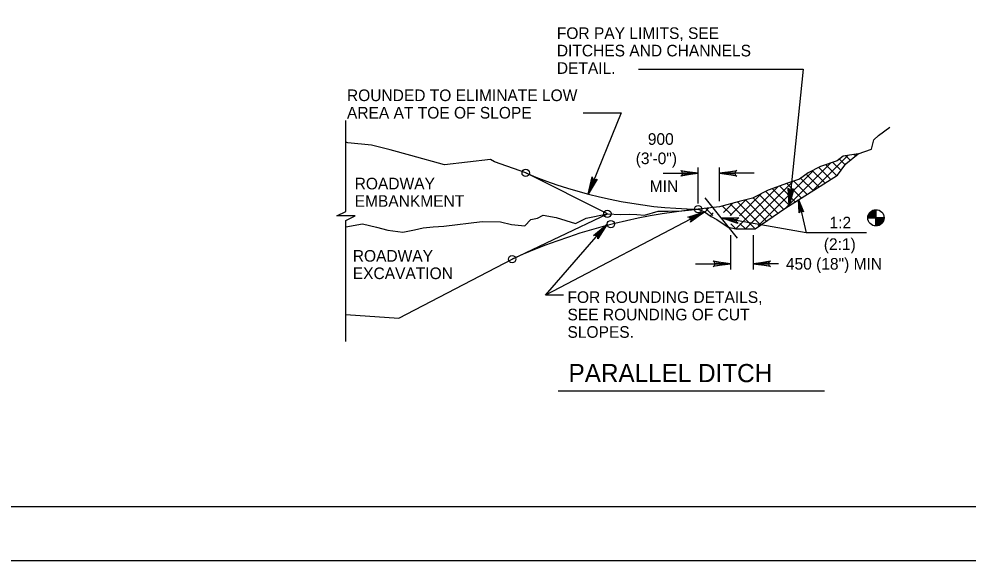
# Model space of a CAD drawing. Extents: x 240 to 1147, y 662 to 1256.
# Drawn here: x 597 to 858.8, y 662 to 811.2 of the extents above; entities that cross this region are included whole.
import ezdxf

# ---------------------------------------------------------------- set-up
doc = ezdxf.new("R2010")
doc.units = 0
for name, color, linetype in [('1', 7, 'Continuous'), ('2', 7, 'Continuous'), ('3', 7, 'Continuous'), ('PLT-BNDY', 7, 'Continuous')]:
    doc.layers.add(name, color=color, linetype=linetype)

msp = doc.modelspace()

# ---------------------------------------------------------------- linework, layer by layer
at = {"layer": '1'}
for points in [[(1065.4425, 677.018625), (1065.4425, 1241.018625), (279.4425, 1241.018625), (279.4425, 677.018625), (1065.4425, 677.018625), (1065.4425, 703.377625), (865.4425, 703.377625), (865.4425, 768.055125), (1065.4425, 768.055125), (1065.4425, 797.018625), (865.4425, 797.018625), (865.4425, 677.018625), (944.244, 677.018625), (944.244, 703.377625), (944.244, 677.018625), (1021.244, 677.018625), (1021.244, 703.377625), (1021.244, 691.061125), (1065.4425, 691.061125)], [(756.089, 767.017125), (755.7225, 766.985875), (753.8515, 763.027625), (756.089, 767.017125), (756.362, 767.158875), (753.8515, 763.027625), (755.2975, 767.154625), (755.05575, 767.423375), (753.8515, 763.027625), (754.9475, 767.733875), (755.05575, 767.423375)], [(779.5995, 769.325625), (779.76825, 768.996375), (784.14125, 768.756875), (779.5995, 769.325625), (779.36625, 769.525625), (784.14125, 768.756875), (779.7725, 768.540125), (779.612, 768.215125), (784.14125, 768.756875), (779.36625, 767.998375), (779.612, 768.215125)], [(794.56825, 768.185875), (794.3995, 768.515125), (790.02875, 768.756875), (794.56825, 768.185875), (794.8015, 767.985875), (790.02875, 768.756875), (794.39525, 768.971375), (794.55575, 769.296375), (790.02875, 768.756875), (794.8015, 769.515125), (794.55575, 769.296375)], [(810.25575, 764.296375), (809.912, 764.163125), (809.22875, 759.838125), (810.25575, 764.296375), (810.47875, 764.508875), (809.22875, 759.838125), (809.45775, 764.204625), (809.1495, 764.396375), (809.22875, 759.838125), (808.95775, 764.663125), (809.1495, 764.396375)], [(812.137, 758.102625), (812.3495, 758.279625), (811.80375, 761.519375), (812.137, 758.102625), (812.02875, 757.898375), (811.80375, 761.519375), (812.68275, 758.358875), (812.9475, 758.296375), (811.80375, 761.519375), (813.1475, 758.150625), (812.9475, 758.296375)], [(781.637, 756.565125), (781.939, 756.352625), (785.9245, 758.165125), (781.637, 756.565125), (781.339, 756.633875), (785.9245, 758.165125), (782.15575, 755.948375), (782.164, 755.585875), (785.9245, 758.165125), (782.0475, 755.279625), (782.164, 755.585875)], [(794.87475, 755.183875), (794.765, 755.535625), (790.5015, 756.527625), (794.87475, 755.183875), (795.0705, 754.946625), (790.5015, 756.527625), (794.83975, 755.986625), (795.054, 756.279625), (790.5015, 756.527625), (795.33275, 756.451125), (795.054, 756.279625)], [(755.66625, 751.715125), (756.0245, 751.625625), (759.0765, 754.765125), (755.66625, 751.715125), (755.362, 751.669375), (759.0765, 754.765125), (756.3725, 751.327625), (756.512, 750.994375), (759.0765, 754.765125), (756.51625, 750.667125), (756.512, 750.994375)], [(788.51, 744.429625), (788.67875, 744.100625), (793.0515, 743.858875), (788.51, 744.429625), (788.27875, 744.627625), (793.0515, 743.858875), (788.68275, 743.644375), (788.5245, 743.317125), (793.0515, 743.858875), (788.27875, 743.100625), (788.5245, 743.317125)], [(803.84125, 743.290125), (803.6725, 743.617125), (799.3015, 743.858875), (803.84125, 743.290125), (804.0745, 743.090125), (799.3015, 743.858875), (803.66825, 744.075625), (803.82875, 744.400625), (799.3015, 743.858875), (804.0745, 744.617125), (803.82875, 744.400625)]]:
    msp.add_lwpolyline(points, dxfattribs=at)
at = {"layer": '2'}
for p, q in [((767.742, 797.449875), (813.0655, 797.449875)), ((813.0655, 797.449875), (809.22875, 759.838125)), ((752.49525, 785.403375), (762.95225, 785.403375)), ((762.95225, 785.403375), (753.8515, 763.027625)), ((815.94525, 764.221375), (825.3765, 773.650625)), ((824.4475, 771.263125), (823.07025, 772.640125)), ((825.91625, 772.446375), (824.8015, 773.558875)), ((827.464, 773.550625), (827.089, 773.925625)), ((784.14125, 760.458875), (784.14125, 770.356875)), ((790.02875, 761.075625), (790.02875, 770.356875)), ((808.314, 759.240125), (820.60575, 771.533875)), ((820.537, 767.217125), (817.41825, 770.335875)), ((822.14125, 768.265125), (819.31, 771.096375)), ((823.4765, 769.581875), (821.29325, 771.765125)), ((759.14125, 757.608875), (736.64125, 768.858875)), ((774.54125, 768.756875), (784.14125, 768.756875)), ((799.62875, 768.756875), (790.02875, 768.756875)), ((800.68075, 754.258875), (815.76825, 769.346375)), ((815.7245, 764.077625), (812.44525, 767.354625)), ((817.32875, 765.123375), (814.10375, 768.348375)), ((818.93275, 766.171375), (815.76, 769.342125)), ((794.4765, 753.358875), (806.1475, 765.029625)), ((797.12875, 753.358875), (810.2515, 766.481875)), ((809.30575, 759.888125), (804.68275, 764.510875)), ((810.91, 760.935875), (806.64125, 765.204625)), ((812.514, 761.981875), (808.5995, 765.896375)), ((814.12025, 763.029625), (810.55775, 766.590125)), ((795.0405, 750.888375), (786.12925, 761.956625)), ((795.54925, 757.083625), (801.62025, 763.154625)), ((804.49125, 756.746375), (799.2725, 761.967125)), ((806.0975, 757.794375), (801.03275, 762.856875)), ((807.7015, 758.840125), (802.79525, 763.748375)), ((785.9495, 758.090125), (787.02025, 759.158875)), ((793.44125, 757.189875), (790.90775, 759.723375)), ((791.151, 757.987875), (793.67025, 760.506875)), ((792.9555, 757.141875), (797.25375, 761.440125)), ((799.67875, 753.604625), (792.9745, 760.308875)), ((801.28275, 754.652625), (795.04125, 760.894375)), ((802.887, 755.700625), (797.16825, 761.419375)), ((732.89125, 745.108875), (759.14125, 757.608875)), ((788.187, 757.142125), (786.2495, 759.079625)), ((787.56, 757.048875), (788.333, 757.821875)), ((830.89875, 756.486375), (835.3885, 756.486375)), ((835.3885, 756.486375), (830.89875, 756.486375)), ((830.89875, 756.484375), (835.3885, 756.484375)), ((835.3885, 756.484375), (830.89875, 756.484375)), ((833.1425, 754.240625), (833.1425, 758.730125)), ((833.1425, 758.728125), (833.1425, 754.240625)), ((833.14475, 754.240625), (833.14475, 758.730125)), ((833.14475, 758.728125), (833.14475, 754.240625)), ((794.6225, 753.358875), (793.152, 754.828875)), ((797.2725, 753.358875), (795.6675, 754.963625)), ((793.0515, 751.758875), (793.0515, 742.258875)), ((799.3015, 751.758875), (799.3015, 742.258875)), ((830.52575, 752.392875), (813.89575, 752.392875)), ((701.64125, 728.858875), (732.89125, 745.108875)), ((783.4515, 743.858875), (793.0515, 743.858875)), ((806.2845, 743.858875), (799.3015, 743.858875)), ((687.1245, 729.894375), (701.64125, 728.858875)), ((745.589, 708.846125), (819.00575, 708.846125))]:
    msp.add_line(p, q, dxfattribs=at)
for points in [[(687.1245, 722.456875), (687.1245, 755.756875), (689.6245, 757.006875), (684.6245, 757.006875), (687.1245, 758.256875), (687.1245, 783.256875)], [(687.1245, 754.021375), (691.63275, 754.827625), (695.487, 753.885875), (698.67875, 753.079625), (702.7995, 752.540125), (705.989, 753.213125), (708.38275, 753.750625), (711.1745, 754.021375), (714.0975, 754.154625), (724.5995, 755.498375), (729.6515, 755.365125), (732.70775, 754.692125), (736.43075, 754.290125), (738.0265, 756.038125), (739.887, 756.440125), (741.48275, 757.248375), (745.0725, 756.575625), (750.389, 754.960875), (753.314, 756.440125), (759.14125, 757.608875), (762.7515, 757.381875), (765.14325, 757.517125), (767.27025, 757.381875), (769.3975, 757.248375), (773.12025, 758.323375), (775.912, 758.323375), (779.635, 758.458875), (784.14125, 758.858875), (785.9245, 758.165125), (787.717, 756.814875), (789.263, 756.010875), (792.39525, 753.885875), (794.5225, 753.481875), (797.4475, 753.481875), (799.839, 753.481875), (808.3475, 759.265125), (816.05775, 764.104625), (822.57025, 768.273375), (824.83075, 771.367125), (828.2475, 774.108875), (831.8765, 775.400625), (832.54125, 777.956875), (833.87025, 779.167125), (836.92875, 781.452625)], [(736.64125, 768.858875), (728.05575, 771.925625), (726.9765, 772.581875), (714.237, 771.052625), (704.9515, 773.673375), (699.337, 775.202625), (694.15375, 776.513125), (687.6765, 777.167125), (687.1245, 777.335875)], [(828.2475, 774.108875), (824.14525, 773.454625), (822.41825, 772.144375), (817.88275, 770.615125), (814.42875, 768.867125), (812.05375, 767.119375), (808.814, 766.027625), (803.41625, 764.063125), (799.0975, 761.877625), (795.4265, 761.004625), (790.02875, 759.475625), (784.14125, 758.858875)], [(811.80375, 761.519375), (813.89575, 752.392875), (790.5015, 756.527625)], [(785.9245, 758.165125), (742.064, 735.221375)], [(833.13625, 758.609375), (832.84675, 758.592625), (832.58, 758.523875), (832.33225, 758.444875), (832.078, 758.321875), (831.83425, 758.165625), (831.60725, 757.973875), (831.43, 757.759375), (831.255, 757.490625), (831.1405, 757.228125), (831.04675, 756.936375), (831.00725, 756.676125), (831.003, 756.478125)], [(833.13625, 758.451125), (832.87175, 758.434375), (832.62375, 758.371875), (832.3925, 758.296875), (832.155, 758.182375), (831.928, 758.036375), (831.71975, 757.861375), (831.55925, 757.663625), (831.39675, 757.413625), (831.2885, 757.171875), (831.203, 756.898875), (831.1675, 756.663625), (831.1635, 756.478125)], [(833.13625, 758.290625), (832.89675, 758.276125), (832.66975, 758.217625), (832.451, 758.146875), (832.23425, 758.042625), (832.02375, 757.907375), (831.83425, 757.748875), (831.6885, 757.569875), (831.53625, 757.338625), (831.4385, 757.115625), (831.35925, 756.863625), (831.326, 756.648875), (831.32175, 756.478125)], [(833.13625, 758.130125), (832.92175, 758.117625), (832.7135, 758.065625), (832.51125, 757.998875), (832.31125, 757.903125), (832.1175, 757.778125), (831.94875, 757.636375), (831.8175, 757.476125), (831.676, 757.261375), (831.5885, 757.059375), (831.5155, 756.828125), (831.48625, 756.634375), (831.48225, 756.478125)], [(833.13625, 757.971875), (832.94675, 757.959375), (832.75725, 757.911375), (832.57175, 757.851125), (832.3885, 757.763625), (832.2135, 757.651125), (832.0635, 757.523875), (831.94675, 757.380125), (831.8175, 757.184375), (831.7385, 757.003125), (831.67175, 756.790625), (831.64475, 756.619875), (831.6405, 756.478125)], [(833.13625, 757.811375), (832.97175, 757.801125), (832.801, 757.759375), (832.63, 757.703125), (832.4675, 757.623875), (832.30725, 757.521875), (832.178, 757.411375), (832.076, 757.286375), (831.95725, 757.109375), (831.88625, 756.946875), (831.826, 756.755125), (831.803, 756.607375), (831.801, 756.478125)], [(833.13625, 757.651125), (832.99675, 757.642625), (832.84475, 757.605125), (832.6905, 757.555125), (832.54475, 757.484375), (832.401, 757.392625), (832.2925, 757.298875), (832.203, 757.192625), (832.09875, 757.032375), (832.03625, 756.890625), (831.98225, 756.717625), (831.9635, 756.592625), (831.95925, 756.478125)], [(833.13625, 757.492625), (833.02175, 757.484375), (832.8905, 757.451125), (832.74875, 757.407375), (832.62375, 757.344875), (832.49675, 757.263625), (832.405, 757.188625), (832.33225, 757.096875), (832.2385, 756.955125), (832.18625, 756.834375), (832.1385, 756.682375), (832.12175, 756.578125), (832.11975, 756.478125)], [(833.13625, 757.332375), (833.04675, 757.326125), (832.93425, 757.298875), (832.80925, 757.257375), (832.701, 757.205125), (832.5925, 757.136375), (832.51975, 757.076125), (832.46125, 757.003125), (832.38, 756.880125), (832.33625, 756.778125), (832.2925, 756.644875), (832.28225, 756.563625), (832.28, 756.478125)], [(833.13625, 757.171875), (833.07175, 757.167625), (832.978, 757.144875), (832.86975, 757.109375), (832.78, 757.065625), (832.68625, 757.007375), (832.63425, 756.963625), (832.5905, 756.909375), (832.51975, 756.803125), (832.48425, 756.721875), (832.44875, 756.609375), (832.4405, 756.551125), (832.4385, 756.478125)], [(833.13625, 757.013625), (833.09475, 757.009375), (833.02175, 756.990625), (832.928, 756.961375), (832.85725, 756.926125), (832.78, 756.878125), (832.74875, 756.851125), (832.71975, 756.815625), (832.66125, 756.726125), (832.63425, 756.665625), (832.605, 756.573875), (832.59875, 756.536375), (832.59875, 756.478125)], [(832.7675, 756.484375), (832.7675, 756.501125), (832.78225, 756.555125), (832.80725, 756.632375), (832.83225, 756.686375), (832.87175, 756.744875), (832.88225, 756.759375), (832.901, 756.773875), (832.96975, 756.819875), (833.01125, 756.836375), (833.08425, 756.859375), (833.09875, 756.861375), (833.1425, 756.863625)], [(833.13625, 756.690625), (833.11125, 756.684375), (833.04675, 756.665625), (833.0135, 756.648875), (832.976, 756.623875), (832.9425, 756.573875), (832.93225, 756.553125), (832.9175, 756.503125), (832.9175, 756.478125)], [(833.09875, 756.478125), (833.101, 756.507375), (833.103, 756.526125), (833.105, 756.526125), (833.11125, 756.536375), (833.1135, 756.536375), (833.13, 756.546875), (833.13, 756.546875)], [(833.51975, 756.486375), (833.51975, 756.469875), (833.505, 756.415625), (833.48, 756.336375), (833.455, 756.284375), (833.4155, 756.226125), (833.405, 756.211375), (833.3885, 756.196875), (833.3175, 756.151125), (833.276, 756.134375), (833.203, 756.111375), (833.1885, 756.109375), (833.14475, 756.107375)], [(833.151, 754.359375), (833.4405, 754.378125), (833.70725, 754.446875), (833.955, 754.526125), (834.20925, 754.648875), (834.453, 754.805125), (834.68225, 754.996875), (834.85725, 755.211375), (835.03225, 755.480125), (835.14875, 755.742625), (835.2405, 756.034375), (835.28, 756.294875), (835.28425, 756.492625)], [(833.151, 754.519875), (833.4155, 754.536375), (833.6635, 754.598875), (833.89475, 754.673875), (834.13225, 754.788625), (834.35925, 754.934375), (834.5675, 755.109375), (834.728, 755.307375), (834.8925, 755.555125), (834.99875, 755.798875), (835.08425, 756.071875), (835.11975, 756.307375), (835.126, 756.492625)], [(833.151, 754.680125), (833.3905, 754.694875), (833.61975, 754.753125), (833.83625, 754.821875), (834.053, 754.928125), (834.2635, 755.063625), (834.453, 755.221875), (834.59875, 755.401125), (834.751, 755.632375), (834.84875, 755.855125), (834.928, 756.107375), (834.96125, 756.321875), (834.9655, 756.492625)], [(833.151, 754.838625), (833.3655, 754.853125), (833.576, 754.905125), (833.776, 754.971875), (833.976, 755.067625), (834.16975, 755.190625), (834.3385, 755.334375), (834.46975, 755.494875), (834.61125, 755.709375), (834.69875, 755.911375), (834.77175, 756.142625), (834.803, 756.336375), (834.805, 756.492625)], [(833.151, 754.998875), (833.3405, 755.011375), (833.53, 755.059375), (833.7175, 755.119875), (833.89875, 755.207375), (834.076, 755.319875), (834.22375, 755.446875), (834.3405, 755.590625), (834.46975, 755.784375), (834.551, 755.967625), (834.6175, 756.180125), (834.6425, 756.348875), (834.64675, 756.492625)], [(833.151, 755.159375), (833.3155, 755.169875), (833.48625, 755.211375), (833.65725, 755.267625), (833.81975, 755.346875), (833.98, 755.448875), (834.11125, 755.559375), (834.2135, 755.684375), (834.33, 755.861375), (834.401, 756.023875), (834.46125, 756.215625), (834.48425, 756.363625), (834.48625, 756.492625)], [(833.151, 755.317625), (833.2905, 755.328125), (833.4425, 755.365625), (833.59675, 755.415625), (833.7425, 755.486375), (833.88625, 755.578125), (833.99675, 755.669875), (834.08425, 755.778125), (834.1885, 755.938625), (834.251, 756.080125), (834.305, 756.253125), (834.326, 756.378125), (834.328, 756.492625)], [(833.151, 755.478125), (833.2655, 755.484375), (833.39875, 755.519875), (833.5385, 755.563625), (833.6635, 755.626125), (833.7905, 755.705125), (833.88225, 755.782375), (833.955, 755.871875), (834.04875, 756.013625), (834.101, 756.136375), (834.14875, 756.288625), (834.1655, 756.392625), (834.1675, 756.492625)], [(833.151, 755.638625), (833.2405, 755.642625), (833.353, 755.671875), (833.478, 755.711375), (833.58625, 755.765625), (833.69675, 755.834375), (833.7675, 755.894875), (833.826, 755.967625), (833.90725, 756.090625), (833.953, 756.192625), (833.99475, 756.323875), (834.00725, 756.405125), (834.00925, 756.492625)], [(833.151, 755.796875), (833.2175, 755.801125), (833.30925, 755.826125), (833.41975, 755.861375), (833.50725, 755.903125), (833.601, 755.963625), (833.653, 756.007375), (833.69675, 756.061375), (833.7675, 756.167625), (833.803, 756.248875), (833.8385, 756.361375), (833.84675, 756.419875), (833.84875, 756.492625)], [(833.151, 755.957375), (833.1925, 755.959375), (833.2655, 755.978125), (833.35925, 756.009375), (833.43, 756.042625), (833.50725, 756.092625), (833.5405, 756.119875), (833.56975, 756.155125), (833.626, 756.242625), (833.653, 756.305125), (833.68225, 756.396875), (833.6885, 756.434375), (833.6905, 756.492625)], [(833.151, 756.278125), (833.178, 756.284375), (833.2405, 756.305125), (833.27375, 756.321875), (833.3135, 756.346875), (833.34475, 756.396875), (833.355, 756.417625), (833.36975, 756.467625), (833.36975, 756.492625)], [(833.1885, 756.492625), (833.1885, 756.463625), (833.18425, 756.444875), (833.18425, 756.442625), (833.176, 756.434375), (833.176, 756.434375), (833.15725, 756.421875), (833.15725, 756.421875)], [(747.064, 735.221375), (742.064, 735.221375), (759.0765, 754.765125)]]:
    msp.add_lwpolyline(points, dxfattribs=at)
for centre, radius in [((736.640417, 768.858125), 1.015435), ((784.140417, 758.858125), 1.015435), ((759.140417, 757.608125), 1.015435), ((833.143012, 756.48598), 2.24484), ((833.143012, 756.484386), 2.24484), ((833.14467, 756.48598), 2.24484), ((833.14467, 756.484386), 2.24484), ((760.092917, 754.764625), 1.015435), ((732.890417, 745.108125), 1.015435)]:
    msp.add_circle(centre, radius, dxfattribs=at)
for centre, radius, start, end in [((786.398894, 887.398393), 128.560107, 247.22928056, 268.99340556), ((800.2654, 596.369552), 163.286716, 95.66733889, 114.369375)]:
    msp.add_arc(centre, radius, start, end, dxfattribs=at)
at = {"layer": 'PLT-BNDY'}
msp.add_lwpolyline([(240.4425, 1256.018625), (1081.4425, 1256.018625), (1081.4425, 662.018625), (240.4425, 662.018625)], close=True, dxfattribs=at)

# ---------------------------------------------------------------- texts
at = {"layer": '1'}
for s, p in [('(3\'-0")', (766.95425, 771.269875)), ('(2:1)', (818.776, 747.647125))]:
    msp.add_text(s, height=3.1999995, dxfattribs=at).set_placement(p)
at = {"layer": '2'}
for s, p in [('900', (770.288835, 776.582125)), ('450 (18") MIN', (808.332019, 742.230375))]:
    msp.add_text(s, height=3.1999995, dxfattribs=at).set_placement(p)
at = {"layer": '3'}
for s, height, p in [('FOR PAY LIMITS, SEE', 3.1999995, (745.221, 805.724875)), ('DITCHES AND CHANNELS', 3.1999995, (745.221, 800.926875)), ('DETAIL.', 3.1999995, (745.221, 796.128875)), ('ROUNDED TO ELIMINATE LOW', 3.1999875, (687.38975, 788.620625)), ('AREA AT TOE OF SLOPE', 3.1999875, (687.38975, 783.820625)), ('ROADWAY', 3.1999875, (689.514, 764.321375)), ('MIN', 3.1999995, (770.81375, 763.608625)), ('EMBANKMENT', 3.1999875, (689.514, 759.521375)), ('1:2', 3.1999995, (820.352, 753.576625)), ('ROADWAY', 3.1999875, (688.99525, 744.417125)), ('EXCAVATION', 3.1999875, (688.99525, 739.617125)), ('FOR ROUNDING DETAILS,', 3.1999995, (748.1515, 733.056875)), ('SEE ROUNDING OF CUT', 3.1999995, (748.1515, 728.258875)), ('SLOPES.', 3.1999995, (748.1515, 723.460875)), ('PARALLEL DITCH', 4.9998615, (748.4475, 711.250625))]:
    msp.add_text(s, height=height, dxfattribs=at).set_placement(p)

doc.saveas('drawing.dxf')
